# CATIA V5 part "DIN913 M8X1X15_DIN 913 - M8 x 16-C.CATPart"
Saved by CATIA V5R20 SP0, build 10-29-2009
Part number: DIN913 M8X1X15_DIN 913 - M8 x 16-C
Revision: ANY
Definition: UNKNOWN
Nomenclature: DIN913 M8X1X15_DIN 913 - M8 x 16-C
Source: Unknown
Bounding box of the stored display mesh (mm): x 0 to 15, y -3.804 to 3.804, z -4 to 4
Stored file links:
  C:\Users\Utente\Desktop\IO LAVORO\3D X SITO CF\CUMSA\3D files CG\CG 603035\DIN913 M8X1X15_DIN 913 - M8 x 16-C.CATPart
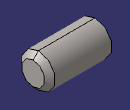
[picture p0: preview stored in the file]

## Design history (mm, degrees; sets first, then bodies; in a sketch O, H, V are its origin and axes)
Body1 "Hex" (main body)
  Solid1: solid without history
